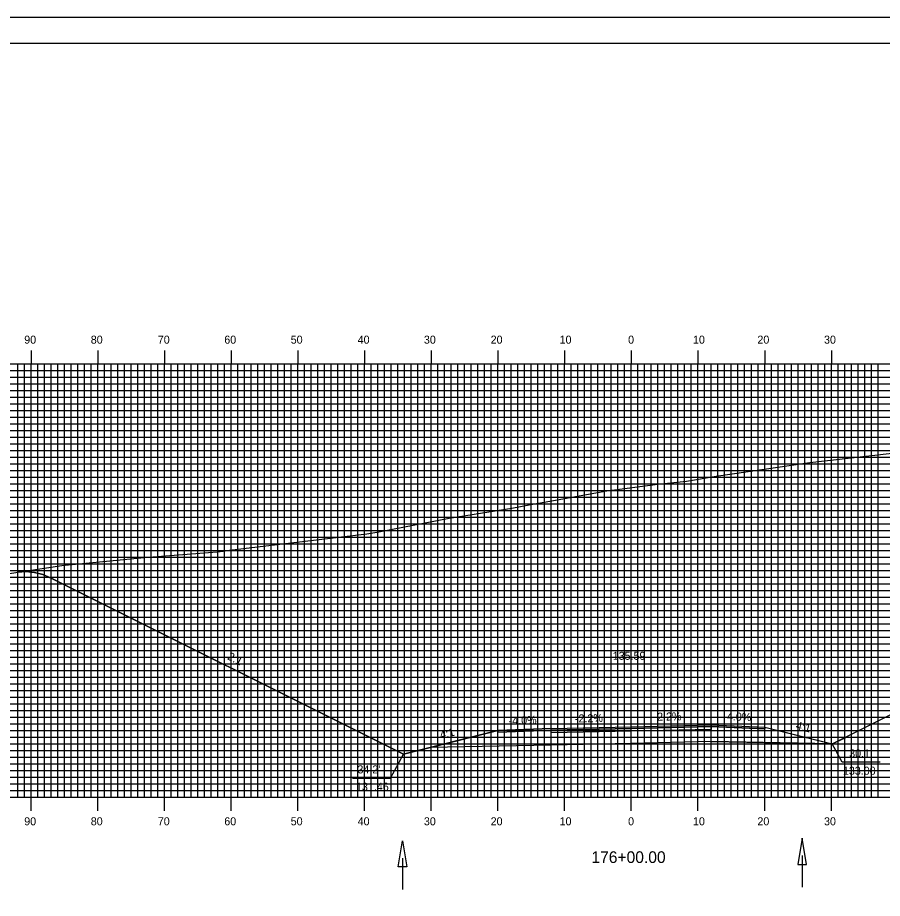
# Model space of a CAD drawing. Extents: x 1784221 to 1784564, y 442591 to 442811.
# Drawn here: x 1784295 to 1784424.7, y 442678.5 to 442810.5 of the extents above; entities that cross this region are included whole.
import ezdxf

# ---------------------------------------------------------------- set-up
doc = ezdxf.new("R2010")
doc.units = 0
for name, color, linetype in [('ANNOTATION', 7, 'Continuous'), ('BORDER', 7, 'Continuous'), ('D_Drainage_Ditch_Line', 7, 'Continuous'), ('D_Roadway_Centerline', 7, 'Continuous'), ('D_Roadway_Centerline_Text', 7, 'Continuous'), ('D_Roadway_Edge_Shoulder', 7, 'Continuous'), ('D_Roadway_Edge_TW', 7, 'Continuous'), ('D_Roadway_Pavement', 7, 'Continuous'), ('D_Roadway_SlopeLines', 7, 'Continuous'), ('D_Roadway_SubGrade', 7, 'Continuous'), ('H_V ANNOTATION', 7, 'Continuous'), ('MAJOR', 7, 'Continuous'), ('MINOR', 7, 'Continuous'), ('PLOT BOUNDARY', 7, 'Continuous'), ('S_Roadway_Centerline', 7, 'Continuous')]:
    doc.layers.add(name, color=color, linetype=linetype)

msp = doc.modelspace()

# ---------------------------------------------------------------- linework, layer by layer
at = {"layer": 'ANNOTATION'}
for points in [[(1784424.3, 442698.92), (1784418.61, 442698.92), (1784417.11, 442701.67)], [(1784345.2, 442696.52), (1784350.89, 442696.52), (1784352.83, 442700.12)]]:
    msp.add_lwpolyline(points, dxfattribs=at)
at = {"layer": 'BORDER'}
msp.add_lwpolyline([(1784237.4, 442596.67), (1784557.4, 442596.67), (1784557.4, 442806.67), (1784237.4, 442806.67)], close=True, dxfattribs=at)
at = {"layer": 'D_Drainage_Ditch_Line'}
for p, q in [((1784352.67, 442684.53), (1784352.67, 442679.83)), ((1784412.6, 442684.92), (1784412.6, 442680.22))]:
    msp.add_line(p, q, dxfattribs=at)
for points in [[(1784353.33, 442683.22), (1784352.02, 442683.22), (1784352.67, 442687.15)], [(1784411.95, 442683.61), (1784413.26, 442683.61), (1784412.6, 442687.54)]]:
    msp.add_lwpolyline(points, close=True, dxfattribs=at)
at = {"layer": 'D_Roadway_Centerline'}
msp.add_lwpolyline([(1784294.99, 442727.41), (1784296.24, 442727.5), (1784297.49, 442727.38), (1784298.74, 442727.06), (1784299.99, 442726.54), (1784352.83, 442700.12), (1784356.83, 442701.12), (1784367, 442703.67), (1784375, 442703.99), (1784387, 442704.25), (1784399, 442704.52), (1784407, 442704.2), (1784417.11, 442701.67), (1784509.14, 442747.63)], dxfattribs=at)
at = {"layer": 'D_Roadway_Edge_Shoulder'}
for points in [[(1784375, 442703.99), (1784367, 442703.67), (1784367, 442703.42), (1784375, 442703.74)], [(1784399, 442704.52), (1784407, 442704.2), (1784407, 442703.95), (1784399, 442704.27)]]:
    msp.add_lwpolyline(points, close=True, dxfattribs=at)
at = {"layer": 'D_Roadway_Edge_TW'}
msp.add_lwpolyline([(1784375, 442703.74), (1784375, 442703.99), (1784387, 442704.25), (1784399, 442704.52), (1784399, 442704.27), (1784387, 442704)], close=True, dxfattribs=at)
at = {"layer": 'D_Roadway_Pavement'}
msp.add_lwpolyline([(1784375, 442703.32), (1784375, 442703.74), (1784387, 442704), (1784399, 442704.27), (1784399, 442703.85), (1784387, 442703.58)], close=True, dxfattribs=at)
at = {"layer": 'D_Roadway_SlopeLines'}
for p, q in [((1784412, 442702.95), (1784417.11, 442701.67)), ((1784417.11, 442701.67), (1784419.17, 442702.65)), ((1784399, 442702.02), (1784407, 442701.86)), ((1784407, 442701.86), (1784417.11, 442701.67))]:
    msp.add_line(p, q, dxfattribs=at)
for points in [[(1784352.83, 442700.12), (1784299.99, 442726.54), (1784298.74, 442727.06), (1784297.49, 442727.38), (1784296.24, 442727.5), (1784294.99, 442727.41)], [(1784367, 442703.67), (1784352.83, 442700.12)], [(1784407, 442704.2), (1784412, 442702.95)]]:
    msp.add_lwpolyline(points, dxfattribs=at)
at = {"layer": 'D_Roadway_SubGrade'}
msp.add_lwpolyline([(1784375, 442701.49), (1784356.83, 442701.12), (1784367, 442703.67), (1784367, 442703.42), (1784375, 442703.74), (1784387, 442704), (1784399, 442704.27), (1784407, 442703.95), (1784407, 442704.2), (1784417.11, 442701.67), (1784399, 442702.02), (1784387, 442701.75)], close=True, dxfattribs=at)
at = {"layer": 'MAJOR'}
for p, q in [((1784297, 442760.67), (1784297, 442758.67)), ((1784307, 442760.67), (1784307, 442758.67)), ((1784317, 442760.67), (1784317, 442758.67)), ((1784327, 442760.67), (1784327, 442758.67)), ((1784337, 442760.67), (1784337, 442758.67)), ((1784347, 442760.67), (1784347, 442758.67)), ((1784357, 442760.67), (1784357, 442758.67)), ((1784367, 442760.67), (1784367, 442758.67)), ((1784377, 442760.67), (1784377, 442758.67)), ((1784387, 442760.67), (1784387, 442758.67)), ((1784397, 442760.67), (1784397, 442758.67)), ((1784407, 442760.67), (1784407, 442758.67)), ((1784417, 442760.67), (1784417, 442758.67)), ((1784247, 442758.67), (1784527, 442758.67)), ((1784247, 442758.67), (1784527, 442758.67)), ((1784297, 442693.67), (1784297, 442758.67)), ((1784307, 442693.67), (1784307, 442758.67)), ((1784317, 442693.67), (1784317, 442758.67)), ((1784327, 442693.67), (1784327, 442758.67)), ((1784337, 442693.67), (1784337, 442758.67)), ((1784347, 442693.67), (1784347, 442758.67)), ((1784357, 442693.67), (1784357, 442758.67)), ((1784367, 442693.67), (1784367, 442758.67)), ((1784377, 442693.67), (1784377, 442758.67)), ((1784387, 442693.67), (1784387, 442758.67)), ((1784397, 442693.67), (1784397, 442758.67)), ((1784407, 442693.67), (1784407, 442758.67)), ((1784417, 442693.67), (1784417, 442758.67)), ((1784247, 442753.67), (1784527, 442753.67)), ((1784247, 442748.67), (1784527, 442748.67)), ((1784247, 442743.67), (1784527, 442743.67)), ((1784247, 442738.67), (1784527, 442738.67)), ((1784247, 442733.67), (1784527, 442733.67)), ((1784247, 442728.67), (1784527, 442728.67)), ((1784247, 442723.67), (1784527, 442723.67)), ((1784247, 442718.67), (1784527, 442718.67)), ((1784247, 442713.67), (1784527, 442713.67)), ((1784247, 442708.67), (1784527, 442708.67)), ((1784247, 442703.67), (1784527, 442703.67)), ((1784247, 442698.67), (1784527, 442698.67)), ((1784247, 442693.67), (1784527, 442693.67)), ((1784247, 442693.67), (1784527, 442693.67)), ((1784297, 442691.66), (1784297, 442693.67)), ((1784307, 442691.66), (1784307, 442693.67)), ((1784317, 442691.66), (1784317, 442693.67)), ((1784327, 442691.66), (1784327, 442693.67)), ((1784337, 442691.66), (1784337, 442693.67)), ((1784347, 442691.66), (1784347, 442693.67)), ((1784357, 442691.66), (1784357, 442693.67)), ((1784367, 442691.66), (1784367, 442693.67)), ((1784377, 442691.66), (1784377, 442693.67)), ((1784387, 442691.66), (1784387, 442693.67)), ((1784397, 442691.66), (1784397, 442693.67)), ((1784407, 442691.66), (1784407, 442693.67)), ((1784417, 442691.66), (1784417, 442693.67))]:
    msp.add_line(p, q, dxfattribs=at)
at = {"layer": 'MINOR'}
for p, q in [((1784247, 442757.67), (1784527, 442757.67)), ((1784295, 442693.67), (1784295, 442758.67)), ((1784296, 442693.67), (1784296, 442758.67)), ((1784298, 442693.67), (1784298, 442758.67)), ((1784299, 442693.67), (1784299, 442758.67)), ((1784300, 442693.67), (1784300, 442758.67)), ((1784301, 442693.67), (1784301, 442758.67)), ((1784302, 442693.67), (1784302, 442758.67)), ((1784303, 442693.67), (1784303, 442758.67)), ((1784304, 442693.67), (1784304, 442758.67)), ((1784305, 442693.67), (1784305, 442758.67)), ((1784306, 442693.67), (1784306, 442758.67)), ((1784308, 442693.67), (1784308, 442758.67)), ((1784309, 442693.67), (1784309, 442758.67)), ((1784310, 442693.67), (1784310, 442758.67)), ((1784311, 442693.67), (1784311, 442758.67)), ((1784312, 442693.67), (1784312, 442758.67)), ((1784313, 442693.67), (1784313, 442758.67)), ((1784314, 442693.67), (1784314, 442758.67)), ((1784315, 442693.67), (1784315, 442758.67)), ((1784316, 442693.67), (1784316, 442758.67)), ((1784318, 442693.67), (1784318, 442758.67)), ((1784319, 442693.67), (1784319, 442758.67)), ((1784320, 442693.67), (1784320, 442758.67)), ((1784321, 442693.67), (1784321, 442758.67)), ((1784322, 442693.67), (1784322, 442758.67)), ((1784323, 442693.67), (1784323, 442758.67)), ((1784324, 442693.67), (1784324, 442758.67)), ((1784325, 442693.67), (1784325, 442758.67)), ((1784326, 442693.67), (1784326, 442758.67)), ((1784328, 442693.67), (1784328, 442758.67)), ((1784329, 442693.67), (1784329, 442758.67)), ((1784330, 442693.67), (1784330, 442758.67)), ((1784331, 442693.67), (1784331, 442758.67)), ((1784332, 442693.67), (1784332, 442758.67)), ((1784333, 442693.67), (1784333, 442758.67)), ((1784334, 442693.67), (1784334, 442758.67)), ((1784335, 442693.67), (1784335, 442758.67)), ((1784336, 442693.67), (1784336, 442758.67)), ((1784338, 442693.67), (1784338, 442758.67)), ((1784339, 442693.67), (1784339, 442758.67)), ((1784340, 442693.67), (1784340, 442758.67)), ((1784341, 442693.67), (1784341, 442758.67)), ((1784342, 442693.67), (1784342, 442758.67)), ((1784343, 442693.67), (1784343, 442758.67)), ((1784344, 442693.67), (1784344, 442758.67)), ((1784345, 442693.67), (1784345, 442758.67)), ((1784346, 442693.67), (1784346, 442758.67)), ((1784348, 442693.67), (1784348, 442758.67)), ((1784349, 442693.67), (1784349, 442758.67)), ((1784350, 442693.67), (1784350, 442758.67)), ((1784351, 442693.67), (1784351, 442758.67)), ((1784352, 442693.67), (1784352, 442758.67)), ((1784353, 442693.67), (1784353, 442758.67)), ((1784354, 442693.67), (1784354, 442758.67)), ((1784355, 442693.67), (1784355, 442758.67)), ((1784356, 442693.67), (1784356, 442758.67)), ((1784358, 442693.67), (1784358, 442758.67)), ((1784359, 442693.67), (1784359, 442758.67)), ((1784360, 442693.67), (1784360, 442758.67)), ((1784361, 442693.67), (1784361, 442758.67)), ((1784362, 442693.67), (1784362, 442758.67)), ((1784363, 442693.67), (1784363, 442758.67)), ((1784364, 442693.67), (1784364, 442758.67)), ((1784365, 442693.67), (1784365, 442758.67)), ((1784366, 442693.67), (1784366, 442758.67)), ((1784368, 442693.67), (1784368, 442758.67)), ((1784369, 442693.67), (1784369, 442758.67)), ((1784370, 442693.67), (1784370, 442758.67)), ((1784371, 442693.67), (1784371, 442758.67)), ((1784372, 442693.67), (1784372, 442758.67)), ((1784373, 442693.67), (1784373, 442758.67)), ((1784374, 442693.67), (1784374, 442758.67)), ((1784375, 442693.67), (1784375, 442758.67)), ((1784376, 442693.67), (1784376, 442758.67)), ((1784378, 442693.67), (1784378, 442758.67)), ((1784379, 442693.67), (1784379, 442758.67)), ((1784380, 442693.67), (1784380, 442758.67)), ((1784381, 442693.67), (1784381, 442758.67)), ((1784382, 442693.67), (1784382, 442758.67)), ((1784383, 442693.67), (1784383, 442758.67)), ((1784384, 442693.67), (1784384, 442758.67)), ((1784385, 442693.67), (1784385, 442758.67)), ((1784386, 442693.67), (1784386, 442758.67)), ((1784388, 442693.67), (1784388, 442758.67)), ((1784389, 442693.67), (1784389, 442758.67)), ((1784390, 442693.67), (1784390, 442758.67)), ((1784391, 442693.67), (1784391, 442758.67)), ((1784392, 442693.67), (1784392, 442758.67)), ((1784393, 442693.67), (1784393, 442758.67)), ((1784394, 442693.67), (1784394, 442758.67)), ((1784395, 442693.67), (1784395, 442758.67)), ((1784396, 442693.67), (1784396, 442758.67)), ((1784398, 442693.67), (1784398, 442758.67)), ((1784399, 442693.67), (1784399, 442758.67)), ((1784400, 442693.67), (1784400, 442758.67)), ((1784401, 442693.67), (1784401, 442758.67)), ((1784402, 442693.67), (1784402, 442758.67)), ((1784403, 442693.67), (1784403, 442758.67)), ((1784404, 442693.67), (1784404, 442758.67)), ((1784405, 442693.67), (1784405, 442758.67)), ((1784406, 442693.67), (1784406, 442758.67)), ((1784408, 442693.67), (1784408, 442758.67)), ((1784409, 442693.67), (1784409, 442758.67)), ((1784410, 442693.67), (1784410, 442758.67)), ((1784411, 442693.67), (1784411, 442758.67)), ((1784412, 442693.67), (1784412, 442758.67)), ((1784413, 442693.67), (1784413, 442758.67)), ((1784414, 442693.67), (1784414, 442758.67)), ((1784415, 442693.67), (1784415, 442758.67)), ((1784416, 442693.67), (1784416, 442758.67)), ((1784418, 442693.67), (1784418, 442758.67)), ((1784419, 442693.67), (1784419, 442758.67)), ((1784420, 442693.67), (1784420, 442758.67)), ((1784421, 442693.67), (1784421, 442758.67)), ((1784422, 442693.67), (1784422, 442758.67)), ((1784423, 442693.67), (1784423, 442758.67)), ((1784424, 442693.67), (1784424, 442758.67)), ((1784247, 442756.67), (1784527, 442756.67)), ((1784247, 442755.67), (1784527, 442755.67)), ((1784247, 442754.67), (1784527, 442754.67)), ((1784247, 442752.67), (1784527, 442752.67)), ((1784247, 442751.67), (1784527, 442751.67)), ((1784247, 442750.67), (1784527, 442750.67)), ((1784247, 442749.67), (1784527, 442749.67)), ((1784247, 442747.67), (1784527, 442747.67)), ((1784247, 442746.67), (1784527, 442746.67)), ((1784247, 442745.67), (1784527, 442745.67)), ((1784247, 442744.67), (1784527, 442744.67)), ((1784247, 442742.67), (1784527, 442742.67)), ((1784247, 442741.67), (1784527, 442741.67)), ((1784247, 442740.67), (1784527, 442740.67)), ((1784247, 442739.67), (1784527, 442739.67)), ((1784247, 442737.67), (1784527, 442737.67)), ((1784247, 442736.67), (1784527, 442736.67)), ((1784247, 442735.67), (1784527, 442735.67)), ((1784247, 442734.67), (1784527, 442734.67)), ((1784247, 442732.67), (1784527, 442732.67)), ((1784247, 442731.67), (1784527, 442731.67)), ((1784247, 442730.67), (1784527, 442730.67)), ((1784247, 442729.67), (1784527, 442729.67)), ((1784247, 442727.67), (1784527, 442727.67)), ((1784247, 442726.67), (1784527, 442726.67)), ((1784247, 442725.67), (1784527, 442725.67)), ((1784247, 442724.67), (1784527, 442724.67)), ((1784247, 442722.67), (1784527, 442722.67)), ((1784247, 442721.67), (1784527, 442721.67)), ((1784247, 442720.67), (1784527, 442720.67)), ((1784247, 442719.67), (1784527, 442719.67)), ((1784247, 442717.67), (1784527, 442717.67)), ((1784247, 442716.67), (1784527, 442716.67)), ((1784247, 442715.67), (1784527, 442715.67)), ((1784247, 442714.67), (1784527, 442714.67)), ((1784247, 442712.67), (1784527, 442712.67)), ((1784247, 442711.67), (1784527, 442711.67)), ((1784247, 442710.67), (1784527, 442710.67)), ((1784247, 442709.67), (1784527, 442709.67)), ((1784247, 442707.67), (1784527, 442707.67)), ((1784247, 442706.67), (1784527, 442706.67)), ((1784247, 442705.67), (1784527, 442705.67)), ((1784247, 442704.67), (1784527, 442704.67)), ((1784247, 442702.67), (1784527, 442702.67)), ((1784247, 442701.67), (1784527, 442701.67)), ((1784247, 442700.67), (1784527, 442700.67)), ((1784247, 442699.67), (1784527, 442699.67)), ((1784247, 442697.67), (1784527, 442697.67)), ((1784247, 442696.67), (1784527, 442696.67)), ((1784247, 442695.67), (1784527, 442695.67)), ((1784247, 442694.67), (1784527, 442694.67))]:
    msp.add_line(p, q, dxfattribs=at)
at = {"layer": 'PLOT BOUNDARY'}
msp.add_lwpolyline([(1784221.21, 442590.55), (1784561.21, 442590.55), (1784561.21, 442810.55), (1784221.21, 442810.55)], close=True, dxfattribs=at)
at = {"layer": 'S_Roadway_Centerline'}
msp.add_lwpolyline([(1784281.85, 442725.43), (1784301.59, 442728.41), (1784303.68, 442728.63), (1784313.97, 442729.62), (1784324.9, 442730.48), (1784325.8, 442730.57), (1784326.77, 442730.69), (1784347.33, 442733.15), (1784349.16, 442733.45), (1784359.69, 442735.5), (1784369.09, 442736.99), (1784371.92, 442737.58), (1784374.79, 442738.06), (1784383.31, 442739.59), (1784390.99, 442740.6), (1784395.27, 442741.06), (1784399.74, 442741.8), (1784413.79, 442743.84), (1784423.05, 442744.92), (1784435.49, 442746.33)], dxfattribs=at)

# ---------------------------------------------------------------- texts
at = {"layer": 'ANNOTATION'}
for s, rotation, p in [('2:1', 333.4349, (1784326.34, 442714.4)), ('-2.2%', 1.2603, (1784378.56, 442704.87)), ('2.2%', 1.2603, (1784390.88, 442705.14)), ('-4.0%', 357.7094, (1784400.79, 442705.25)), ('-4.0%', 2.2906, (1784368.63, 442704.53)), ('4:1', 345.9638, (1784411.59, 442703.91)), ('4:1', 14.0362, (1784358.45, 442702.39))]:
    msp.add_text(s, height=1.2, rotation=rotation, dxfattribs=at).set_placement(p)
for s, p in [("30.1'", (1784419.67, 442699.65)), ("34.2'", (1784345.94, 442697.25)), ('133.00', (1784418.73, 442697.05)), ('131.46', (1784345.72, 442694.65))]:
    msp.add_text(s, height=1.2, dxfattribs=at).set_placement(p)
at = {"layer": 'D_Roadway_Centerline'}
for s, p in [('C', (1784386.99, 442704.25)), ('L', (1784387, 442704.24))]:
    msp.add_text(s, height=0.0146, dxfattribs=at).set_placement(p)
at = {"layer": 'D_Roadway_Centerline_Text'}
msp.add_text('135.59', height=1.2, dxfattribs=at).set_placement((1784384.21, 442714.28))
at = {"layer": 'H_V ANNOTATION'}
for s, height, p in [('90', 1.2, (1784295.97, 442761.67)), ('80', 1.2, (1784305.95, 442761.67)), ('70', 1.2, (1784316, 442761.67)), ('60', 1.2, (1784325.97, 442761.67)), ('50', 1.2, (1784335.93, 442761.67)), ('40', 1.2, (1784345.97, 442761.67)), ('30', 1.2, (1784355.9, 442761.67)), ('20', 1.2, (1784365.91, 442761.67)), ('10', 1.2, (1784376.25, 442761.67)), ('0', 1.2, (1784386.52, 442761.67)), ('10', 1.2, (1784396.25, 442761.67)), ('20', 1.2, (1784405.91, 442761.67)), ('30', 1.2, (1784415.9, 442761.67)), ('90', 1.2, (1784295.97, 442689.47)), ('80', 1.2, (1784305.95, 442689.47)), ('70', 1.2, (1784316, 442689.47)), ('60', 1.2, (1784325.97, 442689.47)), ('50', 1.2, (1784335.93, 442689.47)), ('40', 1.2, (1784345.97, 442689.47)), ('30', 1.2, (1784355.9, 442689.47)), ('20', 1.2, (1784365.91, 442689.47)), ('10', 1.2, (1784376.25, 442689.47)), ('0', 1.2, (1784386.52, 442689.47)), ('10', 1.2, (1784396.25, 442689.47)), ('20', 1.2, (1784405.91, 442689.47)), ('30', 1.2, (1784415.9, 442689.47)), ('176+00.00', 1.75, (1784381.02, 442683.82))]:
    msp.add_text(s, height=height, dxfattribs=at).set_placement(p)

doc.saveas('drawing.dxf')
